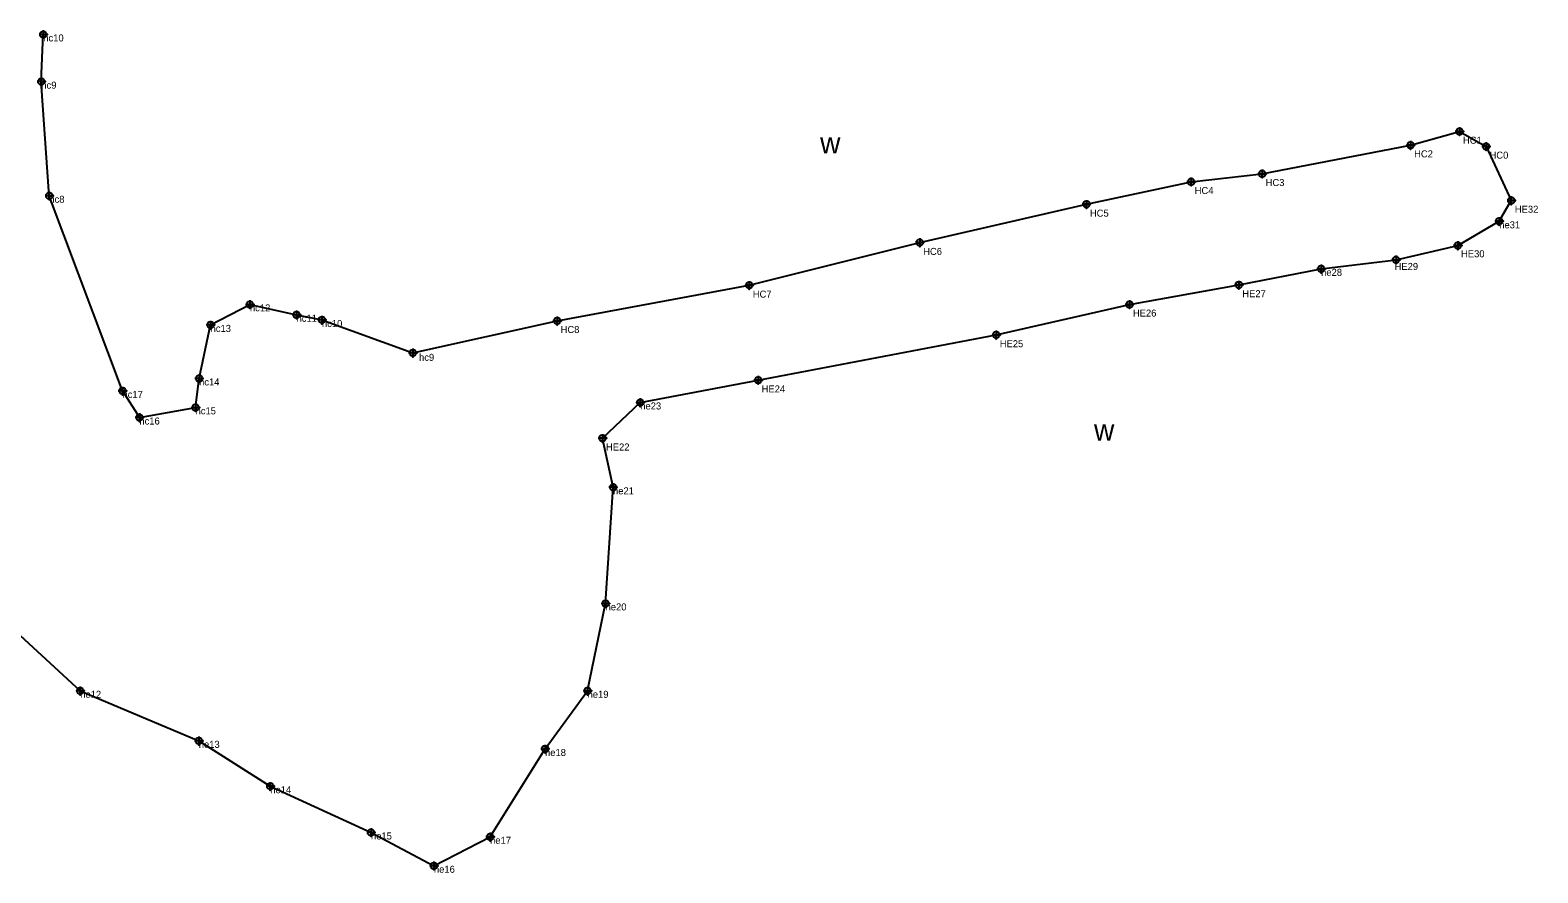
# Model space of a CAD drawing. Extents: x 2184390 to 2187551, y 452846 to 453752.
# Drawn here: x 2184970 to 2186043, y 452846 to 453446 of the extents above; entities that cross this region are included whole.
import ezdxf

# ---------------------------------------------------------------- set-up
doc = ezdxf.new("R2010")
doc.units = 0
for name, color, linetype in [('Exist Environmental Wetland Boundary', 7, 'Continuous'), ('Exist Environmental Wetland Boundary Cogo Comment', 7, 'Continuous'), ('Exist Environmental Wetland Boundary Cogo Point CELL', 7, 'Continuous'), ('Old_Level_52', 7, 'Continuous')]:
    doc.layers.add(name, color=color, linetype=linetype)

msp = doc.modelspace()

# ---------------------------------------------------------------- linework, layer by layer
at = {"layer": 'Exist Environmental Wetland Boundary'}
for points in [[(2185035.5, 453189.3), (2184983.4, 453328.2), (2184977.7, 453409.4), (2184979.1, 453443)], [(2185035.5, 453189.3), (2185047.5, 453170.4), (2185087.5, 453177.6), (2185090, 453198.2), (2185098.2, 453236.3), (2185126.2, 453250.9), (2185159.4, 453243.5), (2185177.5, 453239.8), (2185242.2, 453216.4), (2185344.9, 453239.2), (2185481.7, 453264.5), (2185603, 453294.9), (2185721.7, 453322.1), (2185796.3, 453338.2), (2185846.7, 453343.9), (2185952.5, 453364.2), (2185987.3, 453374), (2186006.2, 453363.3), (2186024.2, 453324.8)], [(2184950.3, 453026.7), (2185005.4, 452975.9), (2185089.8, 452940.3), (2185140.7, 452908), (2185212.4, 452875.1), (2185257.2, 452851.4), (2185297.2, 452872), (2185336.3, 452934.5), (2185366.6, 452975.9), (2185379.4, 453038.1), (2185384.7, 453120.7), (2185377.2, 453155.6), (2185404.1, 453181.1), (2185488, 453197), (2185657.5, 453229.2), (2185752.3, 453250.9), (2185830.2, 453264.7), (2185888.8, 453276.2), (2185942.1, 453282.7), (2185986.1, 453292.8), (2186015.6, 453310), (2186024.2, 453324.8)]]:
    msp.add_lwpolyline(points, dxfattribs=at)
at = {"layer": 'Exist Environmental Wetland Boundary Cogo Point CELL'}
for points in [[(2184979.1, 453446), (2184979.1, 453440), (2184979.1, 453443), (2184982.1, 453443), (2184976.1, 453443)], [(2184977.7, 453412.4), (2184977.7, 453406.4), (2184977.7, 453409.4), (2184980.7, 453409.4), (2184974.7, 453409.4)], [(2185987.3, 453377), (2185987.3, 453371), (2185987.3, 453374), (2185990.3, 453374), (2185984.3, 453374)], [(2185952.5, 453367.2), (2185952.5, 453361.2), (2185952.5, 453364.2), (2185955.5, 453364.2), (2185949.5, 453364.2)], [(2186006.2, 453366.3), (2186006.2, 453360.3), (2186006.2, 453363.3), (2186009.2, 453363.3), (2186003.2, 453363.3)], [(2185846.8, 453346.9), (2185846.8, 453340.9), (2185846.8, 453343.9), (2185849.8, 453343.9), (2185843.8, 453343.9)], [(2185796.3, 453341.2), (2185796.3, 453335.2), (2185796.3, 453338.2), (2185799.3, 453338.2), (2185793.3, 453338.2)], [(2184983.4, 453331.2), (2184983.4, 453325.2), (2184983.4, 453328.2), (2184986.4, 453328.2), (2184980.4, 453328.2)], [(2185721.7, 453325.1), (2185721.7, 453319.1), (2185721.7, 453322.1), (2185724.7, 453322.1), (2185718.7, 453322.1)], [(2186024.2, 453327.8), (2186024.2, 453321.8), (2186024.2, 453324.8), (2186027.2, 453324.8), (2186021.2, 453324.8)], [(2186015.6, 453313), (2186015.6, 453307), (2186015.6, 453310), (2186018.6, 453310), (2186012.6, 453310)], [(2185603, 453297.9), (2185603, 453291.9), (2185603, 453294.9), (2185606, 453294.9), (2185600, 453294.9)], [(2185986.1, 453295.8), (2185986.1, 453289.8), (2185986.1, 453292.8), (2185989.1, 453292.8), (2185983.1, 453292.8)], [(2185888.8, 453279.2), (2185888.8, 453273.2), (2185888.8, 453276.2), (2185891.8, 453276.2), (2185885.8, 453276.2)], [(2185942.1, 453285.7), (2185942.1, 453279.7), (2185942.1, 453282.7), (2185945.1, 453282.7), (2185939.1, 453282.7)], [(2185481.7, 453267.5), (2185481.7, 453261.5), (2185481.7, 453264.5), (2185484.7, 453264.5), (2185478.7, 453264.5)], [(2185830.2, 453267.7), (2185830.2, 453261.7), (2185830.2, 453264.7), (2185833.2, 453264.7), (2185827.2, 453264.7)], [(2185126.2, 453253.9), (2185126.2, 453247.9), (2185126.2, 453250.9), (2185129.2, 453250.9), (2185123.2, 453250.9)], [(2185159.4, 453246.5), (2185159.4, 453240.5), (2185159.4, 453243.5), (2185162.4, 453243.5), (2185156.4, 453243.5)], [(2185752.3, 453253.9), (2185752.3, 453247.9), (2185752.3, 453250.9), (2185755.3, 453250.9), (2185749.3, 453250.9)], [(2185098.2, 453239.3), (2185098.2, 453233.3), (2185098.2, 453236.3), (2185101.2, 453236.3), (2185095.2, 453236.3)], [(2185177.5, 453242.8), (2185177.5, 453236.8), (2185177.5, 453239.8), (2185180.5, 453239.8), (2185174.5, 453239.8)], [(2185344.9, 453242.2), (2185344.9, 453236.2), (2185344.9, 453239.2), (2185347.9, 453239.2), (2185341.9, 453239.2)], [(2185657.5, 453232.2), (2185657.5, 453226.2), (2185657.5, 453229.2), (2185660.5, 453229.2), (2185654.5, 453229.2)], [(2185242.2, 453219.4), (2185242.2, 453213.4), (2185242.2, 453216.4), (2185245.2, 453216.4), (2185239.2, 453216.4)], [(2185090, 453201.2), (2185090, 453195.2), (2185090, 453198.2), (2185093, 453198.2), (2185087, 453198.2)], [(2185488, 453200), (2185488, 453194), (2185488, 453197), (2185491, 453197), (2185485, 453197)], [(2185035.5, 453192.3), (2185035.5, 453186.3), (2185035.5, 453189.3), (2185038.5, 453189.3), (2185032.5, 453189.3)], [(2185404.1, 453184.1), (2185404.1, 453178.1), (2185404.1, 453181.1), (2185407.1, 453181.1), (2185401.1, 453181.1)], [(2185047.5, 453173.4), (2185047.5, 453167.4), (2185047.5, 453170.4), (2185050.5, 453170.4), (2185044.5, 453170.4)], [(2185087.5, 453180.6), (2185087.5, 453174.6), (2185087.5, 453177.6), (2185090.5, 453177.6), (2185084.5, 453177.6)], [(2185377.2, 453158.6), (2185377.2, 453152.6), (2185377.2, 453155.6), (2185380.2, 453155.6), (2185374.2, 453155.6)], [(2185384.7, 453123.7), (2185384.7, 453117.7), (2185384.7, 453120.7), (2185387.7, 453120.7), (2185381.7, 453120.7)], [(2185379.4, 453041.1), (2185379.4, 453035.1), (2185379.4, 453038.1), (2185382.4, 453038.1), (2185376.4, 453038.1)], [(2185005.4, 452978.9), (2185005.4, 452972.9), (2185005.4, 452975.9), (2185008.4, 452975.9), (2185002.4, 452975.9)], [(2185366.6, 452978.9), (2185366.6, 452972.9), (2185366.6, 452975.9), (2185369.6, 452975.9), (2185363.6, 452975.9)], [(2185089.8, 452943.3), (2185089.8, 452937.3), (2185089.8, 452940.3), (2185092.8, 452940.3), (2185086.8, 452940.3)], [(2185336.3, 452937.5), (2185336.3, 452931.5), (2185336.3, 452934.5), (2185339.3, 452934.5), (2185333.3, 452934.5)], [(2185140.7, 452911), (2185140.7, 452905), (2185140.7, 452908), (2185143.7, 452908), (2185137.7, 452908)], [(2185212.4, 452878.1), (2185212.4, 452872.1), (2185212.4, 452875.1), (2185215.4, 452875.1), (2185209.4, 452875.1)], [(2185297.2, 452875), (2185297.2, 452869), (2185297.2, 452872), (2185300.2, 452872), (2185294.2, 452872)], [(2185257.2, 452854.4), (2185257.2, 452848.4), (2185257.2, 452851.4), (2185260.2, 452851.4), (2185254.2, 452851.4)]]:
    msp.add_lwpolyline(points, dxfattribs=at)
for centre in [(2184979.1, 453443), (2184977.7, 453409.4), (2185987.3, 453374), (2185952.5, 453364.2), (2186006.2, 453363.3), (2185846.8, 453343.9), (2185796.3, 453338.2), (2184983.4, 453328.2), (2185721.7, 453322.1), (2186024.2, 453324.8), (2186015.6, 453310), (2185603, 453294.9), (2185986.1, 453292.8), (2185942.1, 453282.7), (2185888.8, 453276.2), (2185481.7, 453264.5), (2185830.2, 453264.7), (2185126.2, 453250.9), (2185752.3, 453250.9), (2185098.2, 453236.3), (2185159.4, 453243.5), (2185177.5, 453239.8), (2185344.9, 453239.2), (2185657.5, 453229.2), (2185242.2, 453216.4), (2185090, 453198.2), (2185488, 453197), (2185035.5, 453189.3), (2185404.1, 453181.1), (2185047.5, 453170.4), (2185087.5, 453177.6), (2185377.2, 453155.6), (2185384.7, 453120.7), (2185379.4, 453038.1), (2185005.4, 452975.9), (2185366.6, 452975.9), (2185089.8, 452940.3), (2185336.3, 452934.5), (2185140.7, 452908), (2185212.4, 452875.1), (2185297.2, 452872), (2185257.2, 452851.4)]:
    msp.add_circle(centre, 2.34, dxfattribs=at)

# ---------------------------------------------------------------- texts
at = {"layer": 'Exist Environmental Wetland Boundary Cogo Comment'}
for s, p in [('hc10', (2184979.1, 453438)), ('hc9', (2184977.7, 453404.4)), ('HC1', (2185989.8, 453365.2)), ('HC2', (2185955, 453355.5)), ('HC0', (2186008.7, 453354.6)), ('HC4', (2185798.8, 453329.4)), ('HC3', (2185849.3, 453335.1)), ('hc8', (2184983.4, 453323.2)), ('HC5', (2185724.2, 453313.3)), ('HE32', (2186026.7, 453316.1)), ('he31', (2186015.6, 453305)), ('HC6', (2185605.5, 453286.1)), ('HE30', (2185988.4, 453284.4)), ('HE29', (2185941.1, 453275.4)), ('he28', (2185888.8, 453271.2)), ('HC7', (2185484.2, 453255.7)), ('HE27', (2185832.7, 453256)), ('hc12', (2185126.2, 453245.9)), ('HE26', (2185754.8, 453242.2)), ('hc13', (2185098.2, 453231.3)), ('hc11', (2185159.4, 453238.5)), ('hc10', (2185177.5, 453234.8)), ('HC8', (2185347.4, 453230.5)), ('HE25', (2185660, 453220.4)), ('hc9', (2185246.6, 453210.7)), ('hc14', (2185090, 453193.2)), ('HE24', (2185490.5, 453188.2)), ('hc17', (2185035.5, 453184.3)), ('hc15', (2185087.5, 453172.6)), ('he23', (2185404.1, 453176.1)), ('hc16', (2185047.5, 453165.4)), ('HE22', (2185379.7, 453146.9)), ('he21', (2185384.7, 453115.7)), ('he20', (2185379.4, 453033.1)), ('he12', (2185005.4, 452970.9)), ('he19', (2185366.6, 452970.9)), ('he13', (2185089.8, 452935.3)), ('he18', (2185336.3, 452929.5)), ('he14', (2185140.7, 452903)), ('he15', (2185212.4, 452870.1)), ('he17', (2185297.2, 452867)), ('he16', (2185257.2, 452846.4))]:
    msp.add_text(s, height=5, dxfattribs=at).set_placement(p)
at = {"layer": 'Old_Level_52'}
for p in [(2185532.1, 453358.3), (2185727.1, 453154)]:
    msp.add_text('w', height=15, dxfattribs=at).set_placement(p)

doc.saveas('drawing.dxf')
